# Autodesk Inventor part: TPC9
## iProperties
Shininess: 64.0
Length Units: 11272
Angle Units: 11279
Time Units: 11290
Mass Units: 11286
Length Display Precision: 3
Angle Display Precision: 2
Compacted: True
Part Number: TPC9
Document SubType Name: Modeling
Created: 2004-08
Designer: Lori
Manufacturer: Standard
Standards Organization: Custom
Density: 0.0
Volumn: 0.0
Area: 0.0
PropertySet Name: Model Information
Control State: 0
Master: False
Checked Out: False
Author: Lori
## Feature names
1. Base1
